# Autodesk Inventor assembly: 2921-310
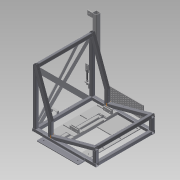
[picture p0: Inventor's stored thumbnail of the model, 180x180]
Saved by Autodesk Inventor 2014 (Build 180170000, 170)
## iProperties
Company: NHTSA/VRTC
Created: 2012-02
Part Number: 2921-310
Document SubType Name: Assembly
Designer: Mike Vanvoorhis
Project: CHILD SIDE IMPACT SLED
Description: BENCH FRAME ASSEMBLY
Mass: 60409 g
Surface Area: 36369.7 cm^2
Volume: 7695.41 cm^3
Density: 7.85 g/cm^3
Design Date: 2012-11-05
Author: Dave Walker
Title: Bench Frame Assembly
Subject: Child Side Impact Sled
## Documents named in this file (24)
- B:\VRTC_DWG\BIO\Non-P572\Child Side-Frontal Impact Sled\Side Impact Sled\Bench_Frame_Assembly.iam
- B:\VRTC_DWG\BIO\Non-P572\Child Side-Frontal Impact Sled\Side Impact Sled\Bench_Base_Mounting_Angle.ipt
- B:\VRTC_DWG\BIO\Non-P572\Child Side-Frontal Impact Sled\Side Impact Sled\Bench_Frame_Tube-1.ipt
- B:\VRTC_DWG\BIO\Non-P572\Child Side-Frontal Impact Sled\Side Impact Sled\Bench_Frame_Tube-2.ipt
- B:\VRTC_DWG\BIO\Non-P572\Child Side-Frontal Impact Sled\Side Impact Sled\Bench_Frame_Tube-3.ipt
- B:\VRTC_DWG\BIO\Non-P572\Child Side-Frontal Impact Sled\Side Impact Sled\Bench_Frame_Tube-4.ipt
- B:\VRTC_DWG\BIO\Non-P572\Child Side-Frontal Impact Sled\Side Impact Sled\Bench_Frame_Tube-5.ipt
- B:\VRTC_DWG\BIO\Non-P572\Child Side-Frontal Impact Sled\Side Impact Sled\Bench_Frame_Tube-6.ipt
- B:\VRTC_DWG\BIO\Non-P572\Child Side-Frontal Impact Sled\Side Impact Sled\Bench_Frame_Tube-7.ipt
- B:\VRTC_DWG\BIO\Non-P572\Child Side-Frontal Impact Sled\Side Impact Sled\Bench_Frame_Tube-9_Assembly.iam
- B:\VRTC_DWG\BIO\Non-P572\Child Side-Frontal Impact Sled\Side Impact Sled\Bench_Bearing_Support_Plate.ipt
- B:\VRTC_DWG\BIO\Non-P572\Child Side-Frontal Impact Sled\Side Impact Sled\Bench_Lower_Anchor_Mounting_Angle.ipt
- B:\VRTC_DWG\BIO\Non-P572\Child Side-Frontal Impact Sled\Side Impact Sled\Bench_Upper_Belt_Mounting_Tube.ipt
- B:\VRTC_DWG\BIO\Non-P572\Child Side-Frontal Impact Sled\Side Impact Sled\Bench_Cross_Brace_Plate.ipt
- B:\VRTC_DWG\BIO\Non-P572\Child Side-Frontal Impact Sled\Side Impact Sled\Bench_Top_Anchor_Brace_Plate.ipt
- B:\VRTC_DWG\BIO\Non-P572\Child Side-Frontal Impact Sled\Side Impact Sled\Bench_Stop_Plate.ipt
- B:\VRTC_DWG\BIO\Non-P572\Child Side-Frontal Impact Sled\Side Impact Sled\D_Ring_Anchor_Part_4.ipt
- B:\VRTC_DWG\BIO\Non-P572\Child Side-Frontal Impact Sled\Side Impact Sled\D_Ring_Anchor_Part_3.ipt
- B:\VRTC_DWG\BIO\Non-P572\Child Side-Frontal Impact Sled\Side Impact Sled\Washer 0.50.ipt
- B:\VRTC_DWG\BIO\Non-P572\Child Side-Frontal Impact Sled\Side Impact Sled\D_Ring_Anchor_Assembly1.iam
- B:\VRTC_DWG\BIO\Non-P572\Child Side-Frontal Impact Sled\Side Impact Sled\Nut Hex 0.5-13.ipt
- B:\VRTC_DWG\BIO\Non-P572\Child Side-Frontal Impact Sled\Side Impact Sled\Light Trap Vane.ipt
- B:\VRTC_DWG\BIO\Non-P572\Child Side-Frontal Impact Sled\Side Impact Sled\Bench_Frame_Tube-8.ipt
- B:\VRTC_DWG\BIO\Non-P572\Child Side-Frontal Impact Sled\Side Impact Sled\Bench Frame Center Stiffener Plate.ipt
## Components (39 placed, 23 different names)
1. Bench_Base_Mounting_Angle:1 — Mate:1, Flush:1, Flush:2
2. Bench_Frame_Tube-1:1 — Mate:1, Flush:1, Flush:2, Flush:3, Flush:4, Flush:5, Flush:6, Mate:2, Mate:3, Flush:7, Flush:8, Mate:5, Flush:9, Flush:10, Mate:7, Flush:13, Mate:20, Flush:20, Flush:21, Flush:28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
3. Bench_Frame_Tube-1:2 — Flush:3, Flush:4, Mate:4, Mate:6, Flush:11, Flush:12, Mate:14, Flush:14, Mate:21, Flush:22, Flush:23, Mate:45, Flush:56, Flush:59, Flush:61, Flush:30, Mate:78
4. Bench_Frame_Tube-2:1 — Flush:5, Flush:6, Mate:2, Flush:29, Flush:55, Flush:60
5. Bench_Frame_Tube-2:2 — Mate:3, Flush:26, Flush:27
6. Bench_Frame_Tube-2:3 — Flush:18, Flush:19, Mate:19
7. Bench_Frame_Tube-8:1 — Mate:26, Flush:7, Flush:8, Mate:4, Mate:46, Mate:48, Flush:45, Mate:76, Flush:69
8. Bench_Frame_Tube-3:1 — Mate:5, Flush:9, Flush:10, Flush:16, Mate:15, Mate:50, Mate:77
9. Bench_Frame_Tube-3:2 — Mate:6, Flush:11, Flush:12, Flush:17, Mate:17, Flush:44, Mate:44, Mate:47, Mate:71, Flush:67, Angle:1
10. Bench_Frame_Tube-4:1 — Mate:7, Flush:13, Flush:15, Mate:16, Mate:23
11. Bench_Frame_Tube-4:2 — Mate:14, Flush:14, Flush:15, Mate:18, Mate:25
12. Bench_Frame_Tube-5:1 — Flush:16, Mate:15, Mate:16, Mate:19
13. Bench_Frame_Tube-5:2 — Flush:17, Mate:17, Mate:18, Flush:18, Flush:19
14. Bench_Frame_Tube-6:1 — Mate:20, Flush:20, Flush:21, Flush:24, Mate:72
15. Bench_Frame_Tube-6:2 — Mate:21, Flush:22, Flush:23, Mate:24, Flush:25
16. Bench_Bearing_Support_Plate:1 — Flush:59, Flush:60, Flush:62, Mate:74, Mate:79, Flush:70
17. Bench_Bearing_Support_Plate:2 — Flush:61, Flush:62, Mate:75
18. Bench_Frame_Tube-7:1 — Flush:24, Mate:23, Flush:26, Flush:27, Mate:72
19. Bench_Frame_Tube-7:2 — Mate:24, Flush:25, Mate:25, Mate:57
20. Bench_Frame_Tube-9_Assembly:1 [sub-assembly] — Flush:28, Mate:27, Flush:29, Mate:29, Flush:39, Mate:37, Mate:38, Flush:40, Mate:39, Mate:40, Flush:41, Flush:42
21. Bench_Frame_Tube-9_Assembly:2 [sub-assembly] — Flush:30, Mate:28, Mate:29
22. Bench Frame Center Stiffener Plate:1 — Mate:78, Mate:79, Flush:70
23. Bench_Lower_Anchor_Mounting_Angle:1 — Flush:39, Mate:37, Flush:43, Mate:43
24. Bench_Lower_Anchor_Mounting_Angle:2 — Mate:38, Flush:40, Mate:43
25. Bench_Lower_Anchor_Mounting_Angle:3 — Mate:40, Flush:42, Mate:42
26. Bench_Lower_Anchor_Mounting_Angle:4 — Mate:39, Flush:41, Mate:41, Mate:42, Flush:43
27. Bench_Upper_Belt_Mounting_Tube:1 — Flush:44, Mate:44, Mate:45, Mate:52, Flush:65, Flush:66, Mate:73
28. Bench_Cross_Brace_Plate:1 — Mate:48, Mate:50, Mate:51
29. Bench_Cross_Brace_Plate:2 — Mate:46, Mate:47, Mate:51, Flush:45
30. Bench_Top_Anchor_Brace_Plate:1 — Mate:52, Flush:46, Flush:47
31. Bench_Stop_Plate:1 — Flush:55, Flush:56, Mate:57
32. D_Ring_Anchor_Part_4:1 — Flush:65, Flush:66, Mate:73
33. D_Ring_Anchor_Part_3:1 — Mate:71, Flush:67, Insert:1, Insert:2, Insert:3
34. Washer 0.50:1 — Insert:1, Insert:4
35. Washer 0.50:2 — Insert:2, Insert:5
36. D_Ring_Anchor_Assembly1:1 [sub-assembly] — Insert:3, Angle:1
37. Nut Hex 0.5-13:1 — Insert:4
38. Nut Hex 0.5-13:2 — Insert:5
39. Light Trap Vane:1 — Mate:76, Flush:69, Mate:77
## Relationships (103: Flush 50, Mate 47, Insert 5, Angle 1)
- Mate:1: Bench_Base_Mounting_Angle:1 ↔ Bench_Frame_Tube-1:1
- Flush:1: Bench_Base_Mounting_Angle:1 ↔ Bench_Frame_Tube-1:1
- Flush:2: Bench_Base_Mounting_Angle:1 ↔ Bench_Frame_Tube-1:1
- Flush:3: Bench_Frame_Tube-1:1 ↔ Bench_Frame_Tube-1:2
- Flush:4: Bench_Frame_Tube-1:1 ↔ Bench_Frame_Tube-1:2
- Flush:5: Bench_Frame_Tube-1:1 ↔ Bench_Frame_Tube-2:1
- Flush:6: Bench_Frame_Tube-1:1 ↔ Bench_Frame_Tube-2:1
- Mate:2: Bench_Frame_Tube-1:1 ↔ Bench_Frame_Tube-2:1
- Mate:3: Bench_Frame_Tube-1:1 ↔ Bench_Frame_Tube-2:2
- Flush:7: Bench_Frame_Tube-1:1 ↔ Bench_Frame_Tube-8:1
- Flush:8: Bench_Frame_Tube-1:1 ↔ Bench_Frame_Tube-8:1
- Mate:4: Bench_Frame_Tube-1:2 ↔ Bench_Frame_Tube-8:1
- Mate:5: Bench_Frame_Tube-1:1 ↔ Bench_Frame_Tube-3:1
- Mate:6: Bench_Frame_Tube-1:2 ↔ Bench_Frame_Tube-3:2
- Flush:9: Bench_Frame_Tube-1:1 ↔ Bench_Frame_Tube-3:1
- Flush:10: Bench_Frame_Tube-1:1 ↔ Bench_Frame_Tube-3:1
- Flush:11: Bench_Frame_Tube-1:2 ↔ Bench_Frame_Tube-3:2
- Flush:12: Bench_Frame_Tube-1:2 ↔ Bench_Frame_Tube-3:2
- Mate:7: Bench_Frame_Tube-1:1 ↔ Bench_Frame_Tube-4:1
- Flush:13: Bench_Frame_Tube-1:1 ↔ Bench_Frame_Tube-4:1
- Mate:14: Bench_Frame_Tube-1:2 ↔ Bench_Frame_Tube-4:2
- Flush:14: Bench_Frame_Tube-1:2 ↔ Bench_Frame_Tube-4:2
- Flush:15: Bench_Frame_Tube-4:1 ↔ Bench_Frame_Tube-4:2
- Flush:16: Bench_Frame_Tube-3:1 ↔ Bench_Frame_Tube-5:1
- Mate:15: Bench_Frame_Tube-3:1 ↔ Bench_Frame_Tube-5:1
- Mate:16: Bench_Frame_Tube-4:1 ↔ Bench_Frame_Tube-5:1
- Flush:17: Bench_Frame_Tube-3:2 ↔ Bench_Frame_Tube-5:2
- Mate:17: Bench_Frame_Tube-3:2 ↔ Bench_Frame_Tube-5:2
- Mate:18: Bench_Frame_Tube-4:2 ↔ Bench_Frame_Tube-5:2
- Flush:18: Bench_Frame_Tube-2:3 ↔ Bench_Frame_Tube-5:2
- Flush:19: Bench_Frame_Tube-2:3 ↔ Bench_Frame_Tube-5:2
- Mate:19: Bench_Frame_Tube-2:3 ↔ Bench_Frame_Tube-5:1
- Mate:20: Bench_Frame_Tube-1:1 ↔ Bench_Frame_Tube-6:1
- Flush:20: Bench_Frame_Tube-1:1 ↔ Bench_Frame_Tube-6:1
- Flush:21: Bench_Frame_Tube-1:1 ↔ Bench_Frame_Tube-6:1
- Mate:21: Bench_Frame_Tube-1:2 ↔ Bench_Frame_Tube-6:2
- Flush:22: Bench_Frame_Tube-1:2 ↔ Bench_Frame_Tube-6:2
- Flush:23: Bench_Frame_Tube-1:2 ↔ Bench_Frame_Tube-6:2
- Flush:24: Bench_Frame_Tube-6:1 ↔ Bench_Frame_Tube-7:1
- Mate:23: Bench_Frame_Tube-4:1 ↔ Bench_Frame_Tube-7:1
- Mate:24: Bench_Frame_Tube-6:2 ↔ Bench_Frame_Tube-7:2
- Flush:25: Bench_Frame_Tube-6:2 ↔ Bench_Frame_Tube-7:2
- Mate:25: Bench_Frame_Tube-4:2 ↔ Bench_Frame_Tube-7:2
- Flush:26: Bench_Frame_Tube-2:2 ↔ Bench_Frame_Tube-7:1
- Mate:26: Bench_Frame_Tube-1:1 ↔ Bench_Frame_Tube-8:1
- Flush:27: Bench_Frame_Tube-2:2 ↔ Bench_Frame_Tube-7:1
- Flush:28: Bench_Frame_Tube-1:1 ↔ Bench_Frame_Tube-9_Assembly:1
- Mate:27: Bench_Frame_Tube-1:1 ↔ Bench_Frame_Tube-9_Assembly:1
- Flush:29: Bench_Frame_Tube-2:1 ↔ Bench_Frame_Tube-9_Assembly:1
- Flush:30: Bench_Frame_Tube-1:2 ↔ Bench_Frame_Tube-9_Assembly:2
- Mate:28: Bench_Frame_Tube-1:1 ↔ Bench_Frame_Tube-9_Assembly:2
- Mate:29: Bench_Frame_Tube-9_Assembly:1 ↔ Bench_Frame_Tube-9_Assembly:2
- Flush:39: Bench_Frame_Tube-9_Assembly:1 ↔ Bench_Lower_Anchor_Mounting_Angle:1
- Mate:37: Bench_Frame_Tube-9_Assembly:1 ↔ Bench_Lower_Anchor_Mounting_Angle:1
- Mate:38: Bench_Frame_Tube-9_Assembly:1 ↔ Bench_Lower_Anchor_Mounting_Angle:2
- Flush:40: Bench_Frame_Tube-9_Assembly:1 ↔ Bench_Lower_Anchor_Mounting_Angle:2
- Mate:39: Bench_Frame_Tube-9_Assembly:1 ↔ Bench_Lower_Anchor_Mounting_Angle:4
- Mate:40: Bench_Frame_Tube-9_Assembly:1 ↔ Bench_Lower_Anchor_Mounting_Angle:3
- Flush:41: Bench_Frame_Tube-9_Assembly:1 ↔ Bench_Lower_Anchor_Mounting_Angle:4
- Flush:42: Bench_Frame_Tube-9_Assembly:1 ↔ Bench_Lower_Anchor_Mounting_Angle:3
- Mate:41: Bench_Frame_Tube-1:1 ↔ Bench_Lower_Anchor_Mounting_Angle:4
- Mate:42: Bench_Lower_Anchor_Mounting_Angle:3 ↔ Bench_Lower_Anchor_Mounting_Angle:4
- Flush:43: Bench_Lower_Anchor_Mounting_Angle:1 ↔ Bench_Lower_Anchor_Mounting_Angle:4
- Mate:43: Bench_Lower_Anchor_Mounting_Angle:1 ↔ Bench_Lower_Anchor_Mounting_Angle:2
- Flush:44: Bench_Frame_Tube-3:2 ↔ Bench_Upper_Belt_Mounting_Tube:1
- Mate:44: Bench_Frame_Tube-3:2 ↔ Bench_Upper_Belt_Mounting_Tube:1
- Mate:45: Bench_Frame_Tube-1:2 ↔ Bench_Upper_Belt_Mounting_Tube:1
- Mate:46: Bench_Frame_Tube-8:1 ↔ Bench_Cross_Brace_Plate:2
- Mate:47: Bench_Frame_Tube-3:2 ↔ Bench_Cross_Brace_Plate:2
- Mate:48: Bench_Frame_Tube-8:1 ↔ Bench_Cross_Brace_Plate:1
- Mate:50: Bench_Frame_Tube-3:1 ↔ Bench_Cross_Brace_Plate:1
- Mate:51: Bench_Cross_Brace_Plate:1 ↔ Bench_Cross_Brace_Plate:2
- Flush:45: Bench_Frame_Tube-8:1 ↔ Bench_Cross_Brace_Plate:2
- Mate:52: Bench_Upper_Belt_Mounting_Tube:1 ↔ Bench_Top_Anchor_Brace_Plate:1
- Flush:46: Bench_Frame_Tube-1:1 ↔ Bench_Top_Anchor_Brace_Plate:1
- Flush:47: Bench_Frame_Tube-1:1 ↔ Bench_Top_Anchor_Brace_Plate:1
- Flush:55: Bench_Frame_Tube-2:1 ↔ Bench_Stop_Plate:1
- Flush:56: Bench_Frame_Tube-1:2 ↔ Bench_Stop_Plate:1
- Mate:57: Bench_Frame_Tube-7:2 ↔ Bench_Stop_Plate:1
- Flush:59: Bench_Frame_Tube-1:2 ↔ Bench_Bearing_Support_Plate:1
- Flush:60: Bench_Frame_Tube-2:1 ↔ Bench_Bearing_Support_Plate:1
- Flush:61: Bench_Frame_Tube-1:2 ↔ Bench_Bearing_Support_Plate:2
- Flush:62: Bench_Bearing_Support_Plate:1 ↔ Bench_Bearing_Support_Plate:2
- Flush:65: Bench_Upper_Belt_Mounting_Tube:1 ↔ D_Ring_Anchor_Part_4:1
- Flush:66: Bench_Upper_Belt_Mounting_Tube:1 ↔ D_Ring_Anchor_Part_4:1
- Mate:71: Bench_Frame_Tube-3:2 ↔ D_Ring_Anchor_Part_3:1
- Flush:67: Bench_Frame_Tube-3:2 ↔ D_Ring_Anchor_Part_3:1
- Insert:1: D_Ring_Anchor_Part_3:1 ↔ Washer 0.50:1
- Insert:2: D_Ring_Anchor_Part_3:1 ↔ Washer 0.50:2
- Insert:3: D_Ring_Anchor_Part_3:1 ↔ D_Ring_Anchor_Assembly1:1
- Angle:1: Bench_Frame_Tube-3:2 ↔ D_Ring_Anchor_Assembly1:1
- Insert:4: Washer 0.50:1 ↔ Nut Hex 0.5-13:1
- Insert:5: Washer 0.50:2 ↔ Nut Hex 0.5-13:2
- Mate:72: Bench_Frame_Tube-6:1 ↔ Bench_Frame_Tube-7:1
- Mate:73: Bench_Upper_Belt_Mounting_Tube:1 ↔ D_Ring_Anchor_Part_4:1
- Mate:74: Bench_Frame_Tube-1:1 ↔ Bench_Bearing_Support_Plate:1
- Mate:75: Bench_Frame_Tube-1:1 ↔ Bench_Bearing_Support_Plate:2
- Mate:76: Bench_Frame_Tube-8:1 ↔ Light Trap Vane:1
- Flush:69: Bench_Frame_Tube-8:1 ↔ Light Trap Vane:1
- Mate:77: Bench_Frame_Tube-3:1 ↔ Light Trap Vane:1
- Mate:78: Bench_Frame_Tube-1:2 ↔ Bench Frame Center Stiffener Plate:1
- Mate:79: Bench_Bearing_Support_Plate:1 ↔ Bench Frame Center Stiffener Plate:1
- Flush:70: Bench_Bearing_Support_Plate:1 ↔ Bench Frame Center Stiffener Plate:1
